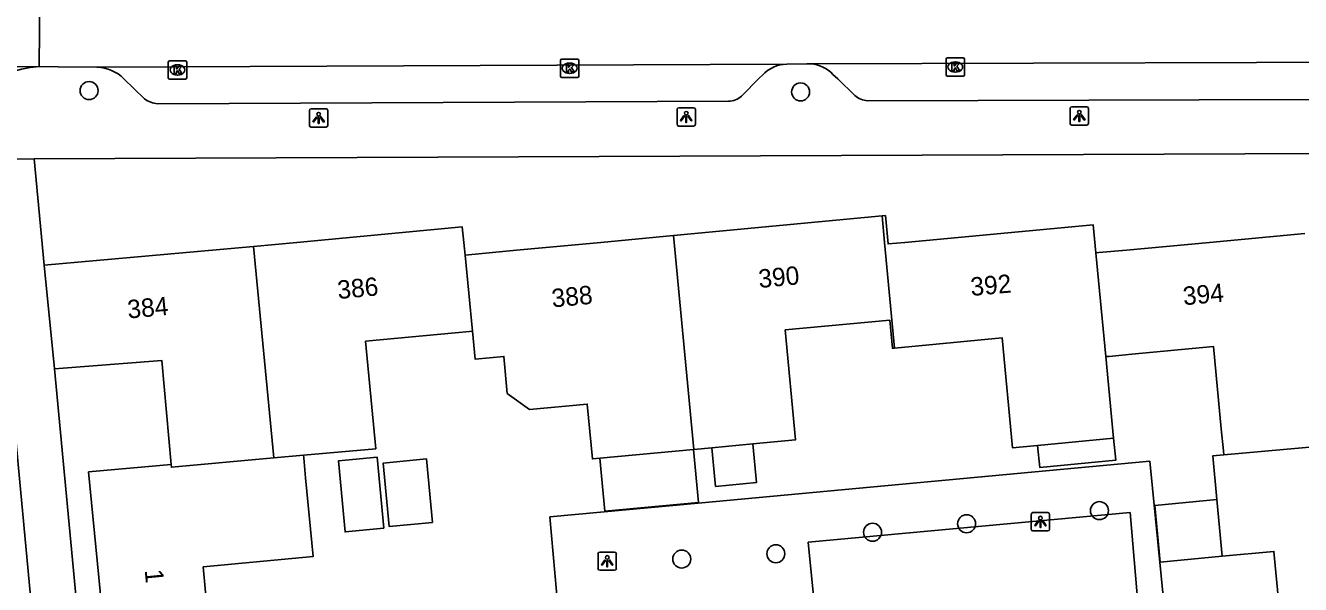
# Model space of a CAD drawing. Extents: x 157793 to 159380, y 380882 to 382313.
# Drawn here: x 158373.3 to 158442.7, y 381231.4 to 381261.8 of the extents above; entities that cross this region are included whole.
import ezdxf

# ---------------------------------------------------------------- set-up
doc = ezdxf.new("R2010")
doc.units = 0
for name, color, linetype in [('IMGEO_Boom', 7, 'Continuous'), ('IMGEO_Kolk', 7, 'Continuous'), ('IMGEO_Lichtpunt', 7, 'Continuous'), ('IMGEO_Muur', 7, 'Continuous'), ('IMGEO_Pand', 7, 'Continuous'), ('IMGEO_Pand_nummerreeks', 7, 'Continuous'), ('IMGEO_Rijbaan_lokaal_gesloten', 7, 'Continuous'), ('IMGEO_Rijbaan_lokaal_open', 7, 'Continuous'), ('IMGEO_Voetpad_open', 7, 'Continuous')]:
    doc.layers.add(name, color=color, linetype=linetype)

msp = doc.modelspace()

# ---------------------------------------------------------------- linework, layer by layer
at = {"layer": 'IMGEO_Boom'}
for centre in [(158376.803, 381258.252), (158415.502, 381258.182), (158431.754, 381235.411), (158424.53, 381234.699), (158419.412, 381234.236), (158414.154, 381233.068), (158409.036, 381232.779)]:
    msp.add_circle(centre, 0.489, dxfattribs=at)
at = {"layer": 'IMGEO_Kolk'}
for p, q in [((158381.187, 381259.876), (158382.039, 381259.876)), ((158402.44, 381259.04), (158402.44, 381259.892)), ((158402.515, 381259.966), (158403.367, 381259.966)), ((158403.441, 381259.892), (158403.441, 381259.04)), ((158423.41, 381259.108), (158423.41, 381259.96)), ((158423.485, 381260.034), (158424.337, 381260.034)), ((158424.411, 381259.96), (158424.411, 381259.108)), ((158381.112, 381258.95), (158381.112, 381259.802)), ((158381.6, 381259.656), (158381.625, 381259.656)), ((158382.113, 381259.802), (158382.113, 381258.95)), ((158402.951, 381259.186), (158402.926, 381259.186)), ((158402.928, 381259.746), (158402.953, 381259.746)), ((158423.921, 381259.254), (158423.896, 381259.254)), ((158423.898, 381259.814), (158423.923, 381259.814)), ((158382.039, 381258.876), (158381.187, 381258.876)), ((158381.623, 381259.096), (158381.598, 381259.096)), ((158403.367, 381258.966), (158402.515, 381258.966)), ((158424.337, 381259.034), (158423.485, 381259.034))]:
    msp.add_line(p, q, dxfattribs=at)
for points in [[(158381.187, 381259.876), (158382.039, 381259.876)], [(158402.44, 381259.04), (158402.44, 381259.892)], [(158402.515, 381259.966), (158403.367, 381259.966)], [(158403.441, 381259.892), (158403.441, 381259.04)], [(158423.41, 381259.108), (158423.41, 381259.96)], [(158423.485, 381260.034), (158424.337, 381260.034)], [(158424.411, 381259.96), (158424.411, 381259.108)], [(158381.112, 381258.95), (158381.112, 381259.802)], [(158381.433, 381259.576), (158381.556, 381259.576), (158381.556, 381259.425), (158381.686, 381259.576), (158381.85, 381259.576), (158381.704, 381259.425), (158381.857, 381259.176), (158381.705, 381259.176), (158381.62, 381259.34), (158381.556, 381259.273), (158381.556, 381259.176), (158381.433, 381259.176), (158381.433, 381259.576)], [(158382.113, 381259.802), (158382.113, 381258.95)], [(158402.761, 381259.666), (158402.884, 381259.666), (158402.884, 381259.515), (158403.014, 381259.666), (158403.178, 381259.666), (158403.032, 381259.515), (158403.185, 381259.266), (158403.033, 381259.266), (158402.948, 381259.43), (158402.884, 381259.363), (158402.884, 381259.266), (158402.761, 381259.266), (158402.761, 381259.666)], [(158423.731, 381259.734), (158423.854, 381259.734), (158423.854, 381259.583), (158423.984, 381259.734), (158424.148, 381259.734), (158424.002, 381259.583), (158424.155, 381259.334), (158424.003, 381259.334), (158423.918, 381259.498), (158423.854, 381259.431), (158423.854, 381259.334), (158423.731, 381259.334), (158423.731, 381259.734)], [(158382.039, 381258.876), (158381.187, 381258.876)], [(158403.367, 381258.966), (158402.515, 381258.966)], [(158424.337, 381259.034), (158423.485, 381259.034)]]:
    msp.add_lwpolyline(points, dxfattribs=at)
for centre, start, end in [((158381.189, 381259.8), 91.55205, 178.44795), ((158381.189, 381259.8), 91.55205, 178.44795), ((158382.037, 381259.8), 1.55205, 88.44795), ((158382.037, 381259.8), 1.55205, 88.44795), ((158402.517, 381259.89), 91.55205, 178.44795), ((158402.517, 381259.89), 91.55205, 178.44795), ((158403.365, 381259.89), 1.55205, 88.44795), ((158403.365, 381259.89), 1.55205, 88.44795), ((158423.487, 381259.958), 91.55205, 178.44795), ((158423.487, 381259.958), 91.55205, 178.44795), ((158424.335, 381259.958), 1.55205, 88.44795), ((158424.335, 381259.958), 1.55205, 88.44795), ((158381.189, 381258.952), 181.55205, 268.44795), ((158381.189, 381258.952), 181.55205, 268.44795), ((158382.037, 381258.952), 271.55205, 358.44795), ((158382.037, 381258.952), 271.55205, 358.44795), ((158402.517, 381259.042), 181.55205, 268.44795), ((158402.517, 381259.042), 181.55205, 268.44795), ((158403.365, 381259.042), 271.55205, 358.44795), ((158403.365, 381259.042), 271.55205, 358.44795), ((158423.487, 381259.11), 181.55205, 268.44795), ((158423.487, 381259.11), 181.55205, 268.44795), ((158424.335, 381259.11), 271.55205, 358.44795), ((158424.335, 381259.11), 271.55205, 358.44795)]:
    msp.add_arc(centre, 0.0765, start, end, dxfattribs=at)
for centre, major_axis, ratio, start_param, end_param in [((158381.599, 381259.376), (-0.387, 0.002), 0.722429, 4.712389, 7.853982), ((158381.624, 381259.376), (-0.39, 0.002), 0.717154, 1.570796, 4.712389), ((158402.927, 381259.466), (-0.387, 0.002), 0.722429, 4.712389, 7.853982), ((158402.952, 381259.466), (-0.39, 0.002), 0.717154, 1.570796, 4.712389), ((158423.897, 381259.534), (-0.387, 0.002), 0.722429, 4.712389, 7.853982), ((158423.922, 381259.534), (-0.39, 0.002), 0.717154, 1.570796, 4.712389)]:
    msp.add_ellipse(centre, major_axis=major_axis, ratio=ratio, start_param=start_param, end_param=end_param, dxfattribs=at)
at = {"layer": 'IMGEO_Lichtpunt'}
for p, q in [((158388.789, 381257.169), (158388.789, 381256.362)), ((158388.789, 381257.169), (158388.789, 381256.362)), ((158389.691, 381257.264), (158388.883, 381257.264)), ((158389.691, 381257.264), (158388.883, 381257.264)), ((158389.785, 381256.362), (158389.785, 381257.169)), ((158389.785, 381256.362), (158389.785, 381257.169)), ((158408.78, 381257.226), (158408.78, 381256.419)), ((158408.78, 381257.226), (158408.78, 381256.419)), ((158409.682, 381257.321), (158408.874, 381257.321)), ((158409.682, 381257.321), (158408.874, 381257.321)), ((158409.776, 381256.419), (158409.776, 381257.226)), ((158409.776, 381256.419), (158409.776, 381257.226)), ((158430.158, 381257.276), (158430.158, 381256.469)), ((158430.158, 381257.276), (158430.158, 381256.469)), ((158431.06, 381257.371), (158430.252, 381257.371)), ((158431.06, 381257.371), (158430.252, 381257.371)), ((158431.154, 381256.469), (158431.154, 381257.276)), ((158431.154, 381256.469), (158431.154, 381257.276)), ((158430.252, 381256.375), (158431.06, 381256.375)), ((158430.252, 381256.375), (158431.06, 381256.375)), ((158388.883, 381256.268), (158389.691, 381256.268)), ((158388.883, 381256.268), (158389.691, 381256.268)), ((158408.874, 381256.325), (158409.682, 381256.325)), ((158408.874, 381256.325), (158409.682, 381256.325)), ((158428.044, 381235.207), (158428.044, 381234.4)), ((158428.044, 381235.207), (158428.044, 381234.4)), ((158428.946, 381235.302), (158428.138, 381235.302)), ((158428.946, 381235.302), (158428.138, 381235.302)), ((158429.04, 381234.4), (158429.04, 381235.207)), ((158429.04, 381234.4), (158429.04, 381235.207)), ((158428.138, 381234.306), (158428.946, 381234.306)), ((158428.138, 381234.306), (158428.946, 381234.306)), ((158404.482, 381233.067), (158404.482, 381232.26)), ((158404.482, 381233.067), (158404.482, 381232.26)), ((158405.384, 381233.162), (158404.576, 381233.162)), ((158405.384, 381233.162), (158404.576, 381233.162)), ((158405.478, 381232.26), (158405.478, 381233.067)), ((158405.478, 381232.26), (158405.478, 381233.067)), ((158404.576, 381232.166), (158405.384, 381232.166)), ((158404.576, 381232.166), (158405.384, 381232.166))]:
    msp.add_line(p, q, dxfattribs=at)
for points in [[(158389.163, 381256.833), (158389.202, 381256.805), (158389.014, 381256.543), (158388.976, 381256.57), (158389.163, 381256.833)], [(158389.265, 381256.785), (158389.312, 381256.785), (158389.312, 381256.463), (158389.265, 381256.463), (158389.265, 381256.785)], [(158389.375, 381256.805), (158389.413, 381256.832), (158389.6, 381256.57), (158389.561, 381256.542), (158389.375, 381256.805)], [(158409.154, 381256.89), (158409.193, 381256.862), (158409.005, 381256.6), (158408.967, 381256.627), (158409.154, 381256.89)], [(158409.256, 381256.842), (158409.303, 381256.842), (158409.303, 381256.52), (158409.256, 381256.52), (158409.256, 381256.842)], [(158409.366, 381256.862), (158409.404, 381256.889), (158409.591, 381256.627), (158409.552, 381256.599), (158409.366, 381256.862)], [(158430.532, 381256.94), (158430.571, 381256.912), (158430.383, 381256.65), (158430.345, 381256.677), (158430.532, 381256.94)], [(158430.634, 381256.892), (158430.681, 381256.892), (158430.681, 381256.57), (158430.634, 381256.57), (158430.634, 381256.892)], [(158430.744, 381256.912), (158430.782, 381256.939), (158430.969, 381256.677), (158430.93, 381256.649), (158430.744, 381256.912)], [(158428.418, 381234.871), (158428.457, 381234.843), (158428.269, 381234.581), (158428.231, 381234.608), (158428.418, 381234.871)], [(158428.63, 381234.843), (158428.668, 381234.87), (158428.855, 381234.608), (158428.816, 381234.58), (158428.63, 381234.843)], [(158428.52, 381234.823), (158428.567, 381234.823), (158428.567, 381234.501), (158428.52, 381234.501), (158428.52, 381234.823)], [(158404.856, 381232.731), (158404.895, 381232.703), (158404.707, 381232.441), (158404.669, 381232.468), (158404.856, 381232.731)], [(158404.958, 381232.683), (158405.005, 381232.683), (158405.005, 381232.361), (158404.958, 381232.361), (158404.958, 381232.683)], [(158405.068, 381232.703), (158405.106, 381232.73), (158405.293, 381232.468), (158405.254, 381232.44), (158405.068, 381232.703)]]:
    msp.add_lwpolyline(points, dxfattribs=at)
for centre in [(158389.288, 381256.967), (158409.279, 381257.024), (158430.657, 381257.074), (158428.543, 381235.005), (158404.981, 381232.865)]:
    msp.add_circle(centre, 0.0994, dxfattribs=at)
for centre, start, end in [((158388.883, 381257.169), 90, 180), ((158388.883, 381257.169), 90, 180), ((158389.691, 381257.169), 0, 90), ((158389.691, 381257.169), 0, 90), ((158408.874, 381257.226), 90, 180), ((158408.874, 381257.226), 90, 180), ((158409.682, 381257.226), 0, 90), ((158409.682, 381257.226), 0, 90), ((158430.252, 381257.276), 90, 180), ((158430.252, 381257.276), 90, 180), ((158431.06, 381257.276), 0, 90), ((158431.06, 381257.276), 0, 90), ((158388.883, 381256.362), 180, 270), ((158388.883, 381256.362), 180, 270), ((158389.691, 381256.362), 270, 0), ((158389.691, 381256.362), 270, 360), ((158408.874, 381256.419), 180, 270), ((158408.874, 381256.419), 180, 270), ((158409.682, 381256.419), 270, 0), ((158409.682, 381256.419), 270, 360), ((158430.252, 381256.469), 180, 270), ((158430.252, 381256.469), 180, 270), ((158431.06, 381256.469), 270, 0), ((158431.06, 381256.469), 270, 360), ((158428.138, 381235.207), 90, 180), ((158428.138, 381235.207), 90, 180), ((158428.946, 381235.207), 0, 90), ((158428.946, 381235.207), 0, 90), ((158428.138, 381234.4), 180, 270), ((158428.138, 381234.4), 180, 270), ((158428.946, 381234.4), 270, 0), ((158428.946, 381234.4), 270, 360), ((158404.576, 381233.067), 90, 180), ((158404.576, 381233.067), 90, 180), ((158405.384, 381233.067), 0, 90), ((158405.384, 381233.067), 0, 90), ((158404.576, 381232.26), 180, 270), ((158404.576, 381232.26), 180, 270), ((158405.384, 381232.26), 270, 0), ((158405.384, 381232.26), 270, 360)]:
    msp.add_arc(centre, 0.0946, start, end, dxfattribs=at)
at = {"layer": 'IMGEO_Muur'}
msp.add_lwpolyline([(158401.867, 381235.072), (158409.933, 381235.822)], dxfattribs=at)
at = {"layer": 'IMGEO_Pand'}
for points in [[(158385.741, 381249.78), (158388.106, 381250), (158397.101, 381250.836), (158397.182, 381250), (158397.249, 381249.305)], [(158408.591, 381250.371), (158419.936, 381251.438)], [(158419.936, 381251.438), (158420.115, 381251.455), (158420.259, 381249.915), (158421.175, 381250), (158431.419, 381250.951), (158431.563, 381249.427)], [(158419.936, 381251.438), (158420.071, 381250), (158420.612, 381244.249)], [(158397.249, 381249.305), (158397.445, 381249.323), (158400.053, 381249.568), (158404.644, 381250), (158408.591, 381250.371)], [(158409.689, 381238.741), (158408.626, 381250), (158408.591, 381250.371)], [(158431.563, 381249.427), (158431.727, 381249.442), (158433.226, 381249.581), (158437.743, 381250), (158442.92, 381250.48)], [(158374.358, 381248.767), (158385.741, 381249.78)], [(158385.741, 381249.78), (158386.85, 381238.28)], [(158431.563, 381249.427), (158432.1, 381243.784)], [(158374.921, 381243.116), (158374.358, 381248.767)], [(158397.249, 381249.305), (158397.65, 381245.17)], [(158420.612, 381244.249), (158420.489, 381244.237), (158420.344, 381245.77), (158414.669, 381245.236), (158415.23, 381239.262), (158412.894, 381239.042)], [(158397.65, 381245.17), (158397.498, 381245.156), (158396.708, 381245.082), (158391.842, 381244.624), (158392.391, 381238.778), (158388.467, 381238.425)], [(158404.586, 381238.26), (158404.178, 381238.222), (158403.897, 381241.207), (158400.754, 381240.911), (158399.55, 381241.787), (158399.361, 381243.795), (158397.797, 381243.648), (158397.65, 381245.17)], [(158428.391, 381238.954), (158427.025, 381238.826), (158426.463, 381244.799), (158420.612, 381244.249)], [(158438.513, 381238.438), (158438.492, 381238.661), (158438.38, 381239.855), (158437.958, 381244.335), (158433.519, 381243.917), (158432.283, 381243.801), (158432.1, 381243.784)], [(158381.271, 381237.926), (158380.752, 381243.577), (158374.921, 381243.116)], [(158432.1, 381243.784), (158432.523, 381239.343)], [(158412.894, 381239.042), (158413.093, 381236.936), (158410.872, 381236.727), (158410.673, 381238.833)], [(158412.894, 381239.042), (158410.673, 381238.833)], [(158432.523, 381239.343), (158432.635, 381238.147), (158428.503, 381237.758), (158428.391, 381238.954)], [(158432.523, 381239.343), (158428.391, 381238.954)], [(158383.543, 381226.677), (158383.01, 381232.352), (158388.984, 381232.914), (158388.582, 381237.189), (158388.48, 381238.281), (158388.467, 381238.425)], [(158388.467, 381238.425), (158386.85, 381238.28)], [(158409.675, 381238.74), (158404.586, 381238.26)], [(158404.586, 381238.26), (158404.857, 381235.386), (158409.94, 381235.854), (158409.675, 381238.74)], [(158409.689, 381238.741), (158409.675, 381238.74)], [(158410.673, 381238.833), (158409.689, 381238.741)], [(158438.139, 381236.012), (158437.916, 381238.384), (158438.513, 381238.438)], [(158438.513, 381238.438), (158444, 381238.93)], [(158381.271, 381237.926), (158376.781, 381237.514), (158377.888, 381226.031), (158379.381, 381226.167)], [(158386.85, 381238.28), (158381.285, 381237.77), (158381.271, 381237.926)], [(158392.84, 381234.453), (158390.729, 381234.255), (158390.366, 381238.119), (158392.477, 381238.318), (158392.84, 381234.453)], [(158395.48, 381234.771), (158393.124, 381234.549), (158392.8, 381237.998), (158395.156, 381238.22), (158395.48, 381234.771)], [(158438.429, 381232.931), (158435.056, 381232.614), (158434.766, 381235.695), (158438.139, 381236.012)], [(158438.429, 381232.931), (158438.139, 381236.012)], [(158441.772, 381227.505), (158441.237, 381233.195), (158438.429, 381232.931)]]:
    msp.add_lwpolyline(points, dxfattribs=at)
at = {"layer": 'IMGEO_Rijbaan_lokaal_gesloten'}
for points in [[(158374.097, 381259.557), (158374.137, 381265.491)], [(158377.232, 381259.519), (158375.117, 381259.544), (158374.097, 381259.557)], [(158414.748, 381259.693), (158377.232, 381259.519)], [(158416.045, 381259.7), (158415.841, 381259.699), (158414.748, 381259.693)], [(158452.413, 381259.816), (158416.045, 381259.7)]]:
    msp.add_lwpolyline(points, dxfattribs=at)
at = {"layer": 'IMGEO_Rijbaan_lokaal_open'}
msp.add_lwpolyline([(158359.295, 381259.485), (158374.097, 381259.557)], dxfattribs=at)
msp.add_arc((158374.304, 381254.641), 4.921, 92.41652, 181.29994, dxfattribs=at)
at = {"layer": 'IMGEO_Voetpad_open'}
for points in [[(158379.818, 381257.812), (158378.701, 381258.893)], [(158413.419, 381259.093), (158413.256, 381258.94), (158412.287, 381257.955)], [(158418.442, 381257.987), (158417.518, 381258.886), (158417.259, 381259.125)], [(158449.192, 381257.786), (158419.153, 381257.698)], [(158411.576, 381257.67), (158380.538, 381257.539)], [(158369.385, 381254.529), (158373.812, 381254.547)], [(158373.812, 381254.547), (158457.221, 381254.886)], [(158374.358, 381248.767), (158373.812, 381254.547)], [(158369.602, 381252.222), (158369.97, 381252.265), (158371.708, 381250.914), (158378.302, 381180.773)], [(158377.638, 381214.267), (158374.921, 381243.116)], [(158402.322, 381229.995), (158401.867, 381235.072), (158409.933, 381235.822), (158434.485, 381238.106), (158435.253, 381230.392)], [(158416.46, 381228.231), (158415.915, 381233.688), (158433.421, 381235.303), (158433.857, 381230.192), (158433.976, 381230.217)]]:
    msp.add_lwpolyline(points, dxfattribs=at)
for centre, radius, start, end in [((158377.192, 381257.389), 2.13, 44.90871, 88.92968), ((158414.809, 381257.786), 1.908, 91.83285, 136.76238), ((158415.951, 381257.933), 1.77, 42.35297, 86.95874), ((158380.573, 381258.716), 1.177, 230.14928, 268.32061), ((158411.576, 381258.701), 1.031, 270.02565, 313.6605), ((158419.21, 381258.857), 1.161, 228.57328, 267.18621)]:
    msp.add_arc(centre, radius, start, end, dxfattribs=at)

# ---------------------------------------------------------------- texts
at = {"layer": 'IMGEO_Pand_nummerreeks'}
for s, rotation, p in [('386', 5.31132, (158390.353, 381246.914)), ('390', 5.37434, (158413.251, 381247.515)), ('392', 4.96181, (158424.779, 381247.083)), ('388', 5.37434, (158402.005, 381246.457)), ('394', 5.29986, (158436.337, 381246.576)), ('384', 5.30465, (158378.932, 381245.853)), ('1', 275.50591, (158379.827, 381232.175))]:
    msp.add_text(s, height=1, rotation=rotation, dxfattribs=at).set_placement(p)

doc.saveas('drawing.dxf')
